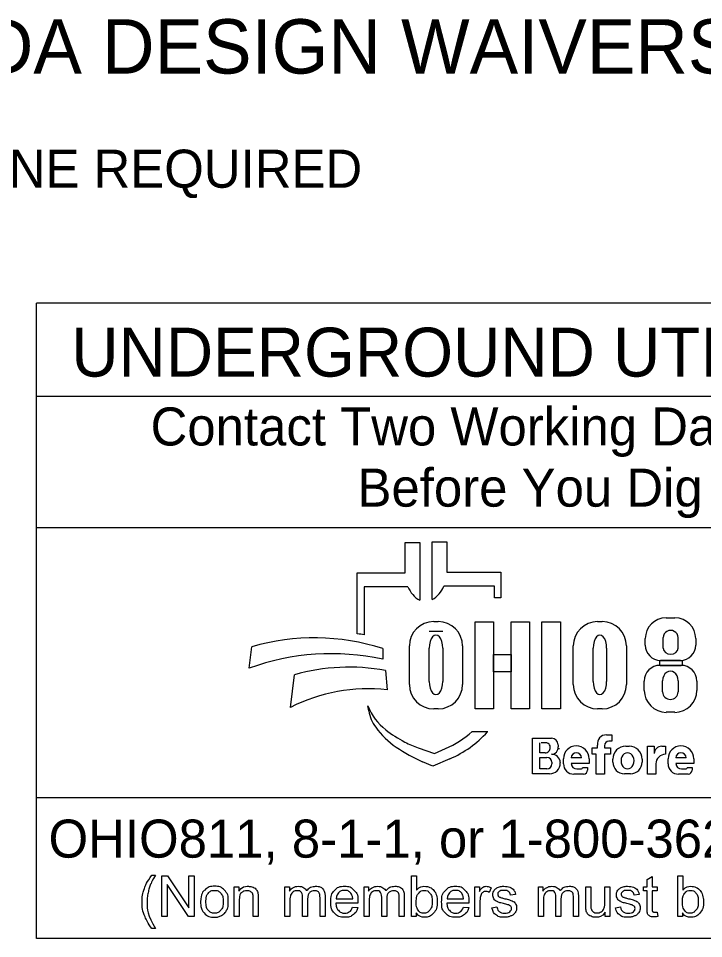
# Model space of a CAD drawing. Extents: x -2.1 to 31.9, y 6.3 to 28.3.
# Drawn here: x 0.246 to 2.766, y 8.487 to 11.873 of the extents above; entities that cross this region are included whole.
import ezdxf

# ---------------------------------------------------------------- set-up
doc = ezdxf.new("R2010")
doc.units = 0
doc.layers.add('SH_Data', color=7, linetype='Continuous')
doc.layers.add('SH_Text', color=7, linetype='Continuous')

msp = doc.modelspace()

# ---------------------------------------------------------------- linework, layer by layer
at = {"layer": 'SH_Data'}
for p, q in [((0.312, 8.4868), (0.312, 10.8243)), ((4.562, 10.8243), (0.312, 10.8243)), ((0.312, 10.4827), (4.562, 10.4827)), ((0.312, 9.9993), (4.562, 9.9993)), ((4.562, 9.0046), (0.312, 9.0046)), ((4.562, 8.4868), (0.312, 8.4868))]:
    msp.add_line(p, q, dxfattribs=at)
at = {"layer": 'SH_Text'}
for p, q in [((1.668, 9.8323), (1.668, 9.9438)), ((1.668, 9.9438), (1.7216, 9.9438)), ((1.7216, 9.9438), (1.7216, 9.7317)), ((1.7673, 9.734), (1.7673, 9.9461)), ((1.7673, 9.9461), (1.8209, 9.9461)), ((1.8209, 9.9461), (1.8209, 9.8346)), ((1.492, 9.6084), (1.492, 9.8323)), ((1.492, 9.8323), (1.668, 9.8323)), ((1.8209, 9.8346), (2.0202, 9.8346)), ((2.0202, 9.8346), (2.0202, 9.7408)), ((1.5173, 9.7808), (1.5173, 9.604)), ((1.6784, 9.7808), (1.5173, 9.7808)), ((1.9969, 9.7831), (1.8105, 9.7831)), ((1.9969, 9.7408), (1.9969, 9.7831)), ((2.0202, 9.7408), (1.9969, 9.7408)), ((1.773, 9.6531), (1.7895, 9.6531)), ((2.376, 9.6531), (2.3926, 9.6531)), ((2.6275, 9.6671), (2.6603, 9.6671)), ((1.8062, 9.6161), (1.7564, 9.6161)), ((2.5512, 9.5665), (2.5512, 9.5908)), ((2.6174, 9.5551), (2.6174, 9.5944)), ((2.6715, 9.5944), (2.6715, 9.5551)), ((2.7366, 9.5908), (2.7366, 9.5665)), ((1.0947, 9.4821), (1.104, 9.5602)), ((1.5853, 9.5537), (1.5853, 9.5149)), ((1.6835, 9.4216), (1.6835, 9.5636)), ((1.7564, 9.433), (1.7564, 9.5553)), ((1.8062, 9.5553), (1.8062, 9.433)), ((1.879, 9.5636), (1.879, 9.4216)), ((2.2865, 9.4216), (2.2865, 9.5636)), ((2.3595, 9.433), (2.3595, 9.5553)), ((2.4092, 9.5553), (2.4092, 9.433)), ((2.482, 9.5636), (2.482, 9.4216)), ((2.6054, 9.4922), (2.6828, 9.4922)), ((2.6806, 9.5105), (2.6072, 9.5105)), ((1.2465, 9.3375), (1.2612, 9.4577)), ((1.5953, 9.4731), (1.6015, 9.4021)), ((2.5475, 9.4002), (2.5475, 9.4343)), ((2.615, 9.3943), (2.615, 9.4352)), ((2.6719, 9.4352), (2.6719, 9.3943)), ((2.7406, 9.4343), (2.7406, 9.4002)), ((1.5342, 9.3246), (1.5311, 9.3426)), ((1.7895, 9.3321), (1.773, 9.3321)), ((2.3926, 9.3321), (2.376, 9.3321)), ((2.6597, 9.3193), (2.6285, 9.3193)), ((1.9145, 9.2488), (1.9719, 9.2488)), ((2.1358, 9.093), (2.1358, 9.2237)), ((2.1358, 9.2237), (2.2069, 9.2237)), ((2.4083, 9.2365), (2.4278, 9.2365)), ((2.4278, 9.2131), (2.4177, 9.2131)), ((2.4278, 9.2365), (2.4278, 9.2135)), ((1.716, 9.1884), (1.7755, 9.1679)), ((1.7755, 9.1679), (1.8165, 9.1857)), ((2.1637, 9.1703), (2.1637, 9.2072)), ((2.1889, 9.2072), (2.1677, 9.2072)), ((2.2307, 9.2), (2.2307, 9.1921)), ((2.3557, 9.1652), (2.3557, 9.1881)), ((2.3557, 9.1881), (2.3751, 9.1881)), ((2.3751, 9.1881), (2.3751, 9.1986)), ((2.4012, 9.1966), (2.4012, 9.1881)), ((2.4012, 9.1881), (2.4227, 9.1881)), ((2.4227, 9.1881), (2.4227, 9.1652)), ((2.4796, 9.1947), (2.4917, 9.1947)), ((2.5598, 9.0918), (2.5598, 9.1945)), ((2.5598, 9.1945), (2.5844, 9.1945)), ((2.5844, 9.1945), (2.5844, 9.1676)), ((2.6116, 9.1945), (2.6255, 9.1945)), ((2.6255, 9.1945), (2.6255, 9.1648)), ((1.8327, 9.1483), (1.7694, 9.1209)), ((2.1831, 9.1703), (2.1637, 9.1703)), ((2.1637, 9.1108), (2.1637, 9.1537)), ((2.1637, 9.1537), (2.1893, 9.1537)), ((2.2503, 9.1298), (2.2503, 9.1482)), ((2.3169, 9.1522), (2.2784, 9.1522)), ((2.3448, 9.1482), (2.3448, 9.1305)), ((2.3707, 9.1652), (2.3557, 9.1652)), ((2.3707, 9.0918), (2.3707, 9.1652)), ((2.4227, 9.1652), (2.4012, 9.1652)), ((2.4012, 9.1652), (2.4012, 9.0918)), ((2.4317, 9.1361), (2.4317, 9.1469)), ((2.5395, 9.1469), (2.5395, 9.1361)), ((2.6352, 9.1298), (2.6352, 9.1482)), ((2.7018, 9.1522), (2.6633, 9.1522)), ((2.7298, 9.1482), (2.7298, 9.1305)), ((1.7694, 9.1209), (1.7321, 9.1373)), ((2.189, 9.1108), (2.1637, 9.1108)), ((2.2074, 9.1356), (2.2074, 9.1292)), ((2.2388, 9.1327), (2.2388, 9.1323)), ((2.3448, 9.1305), (2.2784, 9.1305)), ((2.2993, 9.1113), (2.3135, 9.1113)), ((2.322, 9.1169), (2.3389, 9.1169)), ((2.3389, 9.1169), (2.3389, 9.107)), ((2.5903, 9.1299), (2.5903, 9.0918)), ((2.7298, 9.1305), (2.6633, 9.1305)), ((2.6843, 9.1113), (2.6984, 9.1113)), ((2.707, 9.1169), (2.7238, 9.1169)), ((2.7238, 9.1169), (2.7238, 9.107)), ((2.1994, 9.093), (2.1358, 9.093)), ((2.3237, 9.0918), (2.2883, 9.0918)), ((2.4012, 9.0918), (2.3707, 9.0918)), ((2.4967, 9.0933), (2.4745, 9.0933)), ((2.5903, 9.0918), (2.5598, 9.0918)), ((2.7086, 9.0918), (2.6732, 9.0918))]:
    msp.add_line(p, q, dxfattribs=at)
for points in [[(1.9254, 9.652), (1.9934, 9.652), (1.9934, 9.3321), (1.9254, 9.3321)], [(2.0576, 9.652), (2.1255, 9.652), (2.1255, 9.3321), (2.0576, 9.3321)], [(2.1709, 9.652), (2.2396, 9.652), (2.2396, 9.3321), (2.1709, 9.3321)], [(1.9934, 9.5321), (2.0576, 9.5321), (2.0576, 9.4681), (1.9934, 9.4681)], [(2.6051, 9.5105), (2.6868, 9.5105), (2.6868, 9.492), (2.6051, 9.492)]]:
    msp.add_lwpolyline(points, close=True, dxfattribs=at)
for points in [[(0.7366, 8.7206), (0.7497, 8.7206)], [(0.7733, 8.5679), (0.7733, 8.718), (0.7936, 8.718), (0.8726, 8.6001), (0.8726, 8.718), (0.8916, 8.718), (0.8916, 8.5679), (0.8713, 8.5679), (0.7923, 8.6858), (0.7923, 8.5679), (0.7733, 8.5679)], [(1.7088, 8.5679), (1.6917, 8.5679), (1.6917, 8.718), (1.7101, 8.718), (1.7101, 8.6645)], [(2.5577, 8.5997), (2.5577, 8.6624), (2.5441, 8.6624), (2.5441, 8.6767), (2.5577, 8.6767), (2.5577, 8.7037), (2.5761, 8.7147), (2.5761, 8.6767), (2.5946, 8.6767), (2.5946, 8.6624), (2.5761, 8.6624), (2.5761, 8.5987)], [(2.6878, 8.5679), (2.6708, 8.5679), (2.6708, 8.718), (2.6892, 8.718), (2.6892, 8.6645)], [(1.0393, 8.5679), (1.0393, 8.6767), (1.0559, 8.6767), (1.0559, 8.6613)], [(1.2257, 8.5679), (1.2257, 8.6767), (1.2422, 8.6767), (1.2422, 8.6614)], [(1.5171, 8.5679), (1.5171, 8.6767), (1.5335, 8.6767), (1.5335, 8.6614)], [(1.9248, 8.5679), (1.9248, 8.6767), (1.9414, 8.6767), (1.9414, 8.6602)], [(1.9839, 8.6732), (1.9774, 8.6562)], [(2.1581, 8.5679), (2.1581, 8.6767), (2.1745, 8.6767), (2.1745, 8.6614)], [(2.3324, 8.6093), (2.3324, 8.6767), (2.3508, 8.6767), (2.3508, 8.6164)], [(2.4021, 8.6185), (2.4021, 8.6767), (2.4205, 8.6767), (2.4205, 8.5679), (2.404, 8.5679)], [(1.1276, 8.6348), (1.1276, 8.5679), (1.1092, 8.5679), (1.1092, 8.634)], [(1.3088, 8.6311), (1.3088, 8.5679), (1.2903, 8.5679), (1.2903, 8.6385)], [(1.3732, 8.6426), (1.3732, 8.5679), (1.3548, 8.5679), (1.3548, 8.6364)], [(1.6001, 8.6311), (1.6001, 8.5679), (1.5817, 8.5679), (1.5817, 8.6385)], [(1.6646, 8.6426), (1.6646, 8.5679), (1.6462, 8.5679), (1.6462, 8.6364)], [(2.0738, 8.6486), (2.0558, 8.6462)], [(2.2411, 8.6311), (2.2411, 8.5679), (2.2227, 8.5679), (2.2227, 8.6385)], [(2.3056, 8.6426), (2.3056, 8.5679), (2.2871, 8.5679), (2.2871, 8.6364)], [(2.5284, 8.6486), (2.5103, 8.6462)], [(1.0577, 8.6273), (1.0577, 8.5679), (1.0393, 8.5679)], [(1.2441, 8.6243), (1.2441, 8.5679), (1.2257, 8.5679)], [(1.4944, 8.6176), (1.4133, 8.6176)], [(1.4143, 8.6327), (1.4751, 8.6327)], [(1.4749, 8.603), (1.4939, 8.6006)], [(1.5355, 8.6243), (1.5355, 8.5679), (1.5171, 8.5679)], [(1.9024, 8.6176), (1.8213, 8.6176)], [(1.8223, 8.6327), (1.8831, 8.6327)], [(1.8829, 8.603), (1.9019, 8.6006)], [(1.9433, 8.6249), (1.9433, 8.5679), (1.9248, 8.5679)], [(1.9874, 8.6004), (2.0056, 8.6032)], [(2.1765, 8.6243), (2.1765, 8.5679), (2.1581, 8.5679)], [(2.442, 8.6004), (2.4602, 8.6032)], [(1.7088, 8.5815), (1.7088, 8.5679)], [(2.404, 8.5679), (2.404, 8.584)], [(2.5946, 8.5843), (2.5972, 8.568)], [(2.6878, 8.5815), (2.6878, 8.5679)], [(0.7497, 8.5237), (0.7366, 8.5237)]]:
    msp.add_lwpolyline(points, dxfattribs=at)
for centre, radius, start, end in [((1.7697, 9.8176), 0.0985, 201.9296, 240.7469), ((1.7192, 9.8199), 0.0985, 299.2531, 338.0704), ((1.773, 9.5636), 0.0895, 90, 180), ((1.7895, 9.5636), 0.0895, 0, 90), ((2.376, 9.5636), 0.0895, 90, 180), ((2.3926, 9.5636), 0.0895, 0, 90), ((2.6275, 9.5908), 0.0763, 90, 180), ((2.6603, 9.5908), 0.0763, 0, 90), ((1.3341, 8.7741), 0.8191, 72.1402, 106.3144), ((1.3639, 8.7994), 0.8191, 79.2074, 81.0007), ((2.6072, 9.5665), 0.056, 180, 270), ((2.6806, 9.5665), 0.056, 270, 0), ((1.3972, 8.643), 0.8919, 77.8238, 109.8274), ((1.4611, 8.7533), 0.7322, 79.44, 105.8467), ((2.6054, 9.4343), 0.0579, 90, 180), ((2.6828, 9.4343), 0.0579, 0, 90), ((1.773, 9.4216), 0.0895, 180, 270), ((1.7895, 9.4216), 0.0895, 270, 0), ((2.376, 9.4216), 0.0895, 180, 270), ((2.3926, 9.4216), 0.0895, 270, 0), ((1.5331, 8.7701), 0.6357, 83.8248, 116.8021), ((2.6285, 9.4002), 0.081, 180, 270), ((2.6597, 9.4002), 0.081, 270, 0), ((1.7185, 9.4147), 0.2008, 201.0457, 232.5314), ((1.6755, 9.3487), 0.1433, 189.6817, 216.0884), ((1.8091, 9.4462), 0.3088, 216.0884, 235.7167), ((1.9111, 9.6659), 0.5173, 232.5314, 241.794), ((1.6731, 9.5162), 0.3602, 293.4582, 312.0712), ((1.6731, 9.5162), 0.401, 293.4582, 317.8286), ((1.8259, 9.5071), 0.3371, 241.794, 250.9821), ((2.2069, 9.2), 0.0238, 0, 90), ((2.4083, 9.203), 0.0335, 90, 187.5187), ((2.4177, 9.1966), 0.0165, 90, 180), ((1.9757, 9.6904), 0.6044, 235.7167, 246.2325), ((2.1831, 9.189), 0.0187, 270, 2.0582), ((2.185, 9.1903), 0.0169, 357.8325, 90), ((2.2065, 9.1893), 0.0243, 270, 6.6529), ((2.2171, 9.1878), 0.0175, 347.4023, 0), ((2.2976, 9.1482), 0.0473, 0, 180), ((2.4796, 9.1469), 0.0478, 90, 180), ((2.4917, 9.1469), 0.0478, 0, 90), ((2.6112, 9.1676), 0.0269, 89.2449, 180), ((2.6825, 9.1482), 0.0473, 0, 180), ((2.1893, 9.1356), 0.0181, 0, 90), ((2.2067, 9.1329), 0.0321, 4.0748, 90), ((2.2976, 9.1512), 0.0193, 2.9632, 177.0368), ((2.6252, 9.1299), 0.0349, 89.6033, 180), ((2.6825, 9.1512), 0.0193, 2.9632, 177.0368), ((2.189, 9.1292), 0.0184, 270, 0), ((2.1994, 9.1323), 0.0393, 270, 0), ((2.2058, 9.1327), 0.033, 0, 11.7502), ((2.2883, 9.1298), 0.038, 180, 270), ((2.2993, 9.1323), 0.021, 184.827, 270), ((2.3135, 9.1207), 0.00938, 270, 335.9979), ((2.4745, 9.1361), 0.0428, 180, 270), ((2.4967, 9.1361), 0.0428, 270, 0), ((2.6732, 9.1298), 0.038, 180, 270), ((2.6843, 9.1323), 0.021, 184.827, 270), ((2.6984, 9.1207), 0.00938, 270, 335.9979), ((2.3237, 9.107), 0.0152, 270, 0), ((2.7086, 9.107), 0.0152, 270, 0)]:
    msp.add_arc(centre, radius, start, end, dxfattribs=at)
for centre, major_axis, ratio, start_param, end_param in [((2.6445, 9.5944), (0.0271, 0), 0.969373, 0, 3.141593), ((1.7813, 9.5553), (0, 0.0484), 0.514403, 4.712389, 7.853982), ((2.3843, 9.5553), (0, 0.0484), 0.514403, 4.712389, 7.853982), ((2.6445, 9.5551), (0.0271, 0), 0.818453, 3.141593, 6.283185), ((2.6435, 9.4352), (0, 0.0358), 0.794529, 4.712389, 7.853982), ((1.7813, 9.433), (0, 0.0484), 0.514403, 1.570796, 4.712389), ((2.3843, 9.433), (0, 0.0484), 0.514403, 1.570796, 4.712389), ((2.6435, 9.3943), (0.0284, 0), 0.959837, 3.141593, 6.283185), ((2.4861, 9.1415), (0, 0.029), 0.832186, 4.712389, 7.853982), ((2.4861, 9.1415), (0, 0.0302), 0.797287, 1.570796, 4.712389)]:
    msp.add_ellipse(centre, major_axis=major_axis, ratio=ratio, start_param=start_param, end_param=end_param, dxfattribs=at)
for points in [[(0.7366, 8.5237), (0.7213, 8.543), (0.7107, 8.5688), (0.7002, 8.5946), (0.7002, 8.6222), (0.7002, 8.6466), (0.7081, 8.6689), (0.7173, 8.6948), (0.7366, 8.7206)], [(0.7497, 8.7206), (0.7374, 8.6993), (0.7334, 8.6901), (0.7271, 8.676), (0.7236, 8.6606), (0.7192, 8.6415), (0.7192, 8.6221), (0.7192, 8.5729), (0.7497, 8.5237)], [(0.9158, 8.6223), (0.9158, 8.6525), (0.9326, 8.667), (0.9466, 8.6791), (0.9668, 8.6791), (0.9892, 8.6791), (1.0034, 8.6644), (1.0176, 8.6497), (1.0176, 8.6238), (1.0176, 8.6029), (1.0114, 8.5908), (1.0051, 8.5788), (0.993, 8.5721), (0.981, 8.5655), (0.9668, 8.5655), (0.9439, 8.5655), (0.9299, 8.5801), (0.9158, 8.5948), (0.9158, 8.6223)], [(1.0559, 8.6613), (1.0678, 8.6791), (1.0905, 8.6791), (1.1003, 8.6791), (1.1085, 8.6756), (1.1168, 8.6721), (1.1209, 8.6663), (1.125, 8.6606), (1.1266, 8.6527), (1.1276, 8.6476), (1.1276, 8.6348)], [(1.2422, 8.6614), (1.2473, 8.6694), (1.2558, 8.6742), (1.2643, 8.6791), (1.2752, 8.6791), (1.2873, 8.6791), (1.295, 8.6741), (1.3027, 8.6691), (1.3059, 8.66), (1.3188, 8.6791), (1.3396, 8.6791), (1.3558, 8.6791), (1.3645, 8.6702), (1.3732, 8.6612), (1.3732, 8.6426)], [(1.4939, 8.6006), (1.4894, 8.5839), (1.4772, 8.5747), (1.465, 8.5655), (1.4461, 8.5655), (1.4222, 8.5655), (1.4083, 8.5802), (1.3943, 8.5949), (1.3943, 8.6214), (1.3943, 8.6488), (1.4084, 8.664), (1.4225, 8.6791), (1.4451, 8.6791), (1.4669, 8.6791), (1.4807, 8.6643), (1.4945, 8.6494), (1.4945, 8.6225), (1.4945, 8.6208), (1.4944, 8.6176)], [(1.5335, 8.6614), (1.5387, 8.6694), (1.5472, 8.6742), (1.5557, 8.6791), (1.5665, 8.6791), (1.5786, 8.6791), (1.5864, 8.6741), (1.5941, 8.6691), (1.5973, 8.66), (1.6102, 8.6791), (1.6309, 8.6791), (1.6471, 8.6791), (1.6559, 8.6702), (1.6646, 8.6612), (1.6646, 8.6426)], [(1.7101, 8.6645), (1.7218, 8.6791), (1.7399, 8.6791), (1.75, 8.6791), (1.7589, 8.6751), (1.7679, 8.671), (1.7737, 8.6637), (1.7795, 8.6564), (1.7827, 8.6461), (1.786, 8.6357), (1.786, 8.6239), (1.786, 8.596), (1.7722, 8.5807), (1.7584, 8.5655), (1.739, 8.5655), (1.7197, 8.5655), (1.7088, 8.5815)], [(1.9019, 8.6006), (1.8974, 8.5839), (1.8852, 8.5747), (1.873, 8.5655), (1.8541, 8.5655), (1.8302, 8.5655), (1.8163, 8.5802), (1.8023, 8.5949), (1.8023, 8.6214), (1.8023, 8.6488), (1.8164, 8.664), (1.8305, 8.6791), (1.8531, 8.6791), (1.8749, 8.6791), (1.8887, 8.6643), (1.9025, 8.6494), (1.9025, 8.6225), (1.9025, 8.6208), (1.9024, 8.6176)], [(1.9414, 8.6602), (1.9478, 8.6718), (1.9531, 8.6754), (1.9585, 8.6791), (1.965, 8.6791), (1.9743, 8.6791), (1.9839, 8.6732)], [(2.0056, 8.6032), (2.0072, 8.5923), (2.0142, 8.5864), (2.0213, 8.5806), (2.0339, 8.5806), (2.0466, 8.5806), (2.0528, 8.5858), (2.059, 8.5909), (2.059, 8.5979), (2.059, 8.6042), (2.0535, 8.6078), (2.0497, 8.6102), (2.0346, 8.614), (2.0143, 8.6192), (2.0065, 8.6229), (1.9986, 8.6266), (1.9946, 8.6332), (1.9905, 8.6398), (1.9905, 8.6478), (1.9905, 8.6551), (1.9939, 8.6613), (1.9972, 8.6675), (2.0029, 8.6716), (2.0073, 8.6747), (2.0147, 8.6769), (2.0221, 8.6791), (2.0306, 8.6791), (2.0435, 8.6791), (2.0532, 8.6754), (2.0629, 8.6717), (2.0675, 8.6654), (2.0721, 8.6591), (2.0738, 8.6486)], [(2.1745, 8.6614), (2.1797, 8.6694), (2.1882, 8.6742), (2.1967, 8.6791), (2.2075, 8.6791), (2.2196, 8.6791), (2.2274, 8.6741), (2.2351, 8.6691), (2.2383, 8.66), (2.2512, 8.6791), (2.2719, 8.6791), (2.2881, 8.6791), (2.2969, 8.6702), (2.3056, 8.6612), (2.3056, 8.6426)], [(2.4602, 8.6032), (2.4617, 8.5923), (2.4688, 8.5864), (2.4758, 8.5806), (2.4885, 8.5806), (2.5012, 8.5806), (2.5074, 8.5858), (2.5135, 8.5909), (2.5135, 8.5979), (2.5135, 8.6042), (2.5081, 8.6078), (2.5043, 8.6102), (2.4892, 8.614), (2.4689, 8.6192), (2.4611, 8.6229), (2.4532, 8.6266), (2.4492, 8.6332), (2.4451, 8.6398), (2.4451, 8.6478), (2.4451, 8.6551), (2.4484, 8.6613), (2.4518, 8.6675), (2.4575, 8.6716), (2.4618, 8.6747), (2.4693, 8.6769), (2.4767, 8.6791), (2.4852, 8.6791), (2.498, 8.6791), (2.5077, 8.6754), (2.5174, 8.6717), (2.5221, 8.6654), (2.5267, 8.6591), (2.5284, 8.6486)], [(2.6892, 8.6645), (2.7009, 8.6791), (2.719, 8.6791), (2.729, 8.6791), (2.738, 8.6751), (2.747, 8.671), (2.7527, 8.6637), (2.7585, 8.6564), (2.7618, 8.6461), (2.7651, 8.6357), (2.7651, 8.6239), (2.7651, 8.596), (2.7513, 8.5807), (2.7374, 8.5655), (2.7181, 8.5655), (2.6988, 8.5655), (2.6878, 8.5815)], [(0.9348, 8.6223), (0.9348, 8.6014), (0.9439, 8.591), (0.953, 8.5806), (0.9668, 8.5806), (0.9805, 8.5806), (0.9896, 8.591), (0.9986, 8.6015), (0.9986, 8.6229), (0.9986, 8.6431), (0.9895, 8.6535), (0.9804, 8.6639), (0.9668, 8.6639), (0.953, 8.6639), (0.9439, 8.6536), (0.9348, 8.6432), (0.9348, 8.6223)], [(1.1092, 8.634), (1.1092, 8.6453), (1.1071, 8.6509), (1.1049, 8.6564), (1.0994, 8.6598), (1.0939, 8.6631), (1.0866, 8.6631), (1.0748, 8.6631), (1.0663, 8.6556), (1.0577, 8.6482), (1.0577, 8.6273)], [(1.2903, 8.6385), (1.2903, 8.6508), (1.2858, 8.657), (1.2813, 8.6631), (1.2711, 8.6631), (1.2633, 8.6631), (1.2567, 8.659), (1.2501, 8.6549), (1.2471, 8.647), (1.2441, 8.6391), (1.2441, 8.6243)], [(1.3548, 8.6364), (1.3548, 8.6474), (1.353, 8.6523), (1.3512, 8.6572), (1.3465, 8.6601), (1.3418, 8.6631), (1.3354, 8.6631), (1.3239, 8.6631), (1.3164, 8.6555), (1.3088, 8.6478), (1.3088, 8.6311)], [(1.4751, 8.6327), (1.4738, 8.6464), (1.4681, 8.6533), (1.4593, 8.664), (1.4453, 8.664), (1.4325, 8.664), (1.4239, 8.6555), (1.4152, 8.647), (1.4143, 8.6327)], [(1.5817, 8.6385), (1.5817, 8.6508), (1.5772, 8.657), (1.5727, 8.6631), (1.5624, 8.6631), (1.5547, 8.6631), (1.548, 8.659), (1.5414, 8.6549), (1.5385, 8.647), (1.5355, 8.6391), (1.5355, 8.6243)], [(1.6462, 8.6364), (1.6462, 8.6474), (1.6444, 8.6523), (1.6426, 8.6572), (1.6379, 8.6601), (1.6331, 8.6631), (1.6268, 8.6631), (1.6153, 8.6631), (1.6077, 8.6555), (1.6001, 8.6478), (1.6001, 8.6311)], [(1.7085, 8.6231), (1.7085, 8.6035), (1.7139, 8.5948), (1.7225, 8.5806), (1.7374, 8.5806), (1.7494, 8.5806), (1.7582, 8.5911), (1.767, 8.6016), (1.767, 8.6224), (1.767, 8.6437), (1.7586, 8.6539), (1.7502, 8.664), (1.7382, 8.664), (1.7261, 8.664), (1.7173, 8.6535), (1.7085, 8.643), (1.7085, 8.6231)], [(1.8831, 8.6327), (1.8818, 8.6464), (1.8761, 8.6533), (1.8673, 8.664), (1.8532, 8.664), (1.8405, 8.664), (1.8319, 8.6555), (1.8232, 8.647), (1.8223, 8.6327)], [(1.9774, 8.6562), (1.9707, 8.6601), (1.964, 8.6601), (1.958, 8.6601), (1.9532, 8.6565), (1.9484, 8.6529), (1.9463, 8.6464), (1.9433, 8.6366), (1.9433, 8.6249)], [(2.0558, 8.6462), (2.0545, 8.6546), (2.0486, 8.6593), (2.0427, 8.664), (2.032, 8.664), (2.0193, 8.664), (2.0138, 8.6598), (2.0084, 8.6556), (2.0084, 8.65), (2.0084, 8.6464), (2.0106, 8.6435), (2.0129, 8.6405), (2.0177, 8.6386), (2.0205, 8.6375), (2.034, 8.6339), (2.0536, 8.6286), (2.0614, 8.6253), (2.0691, 8.622), (2.0735, 8.6156), (2.078, 8.6093), (2.078, 8.5999), (2.078, 8.5907), (2.0726, 8.5825), (2.0672, 8.5744), (2.057, 8.5699), (2.0469, 8.5655), (2.034, 8.5655), (2.0128, 8.5655), (2.0017, 8.5743), (1.9905, 8.5831), (1.9874, 8.6004)], [(2.2227, 8.6385), (2.2227, 8.6508), (2.2182, 8.657), (2.2137, 8.6631), (2.2034, 8.6631), (2.1957, 8.6631), (2.189, 8.659), (2.1824, 8.6549), (2.1795, 8.647), (2.1765, 8.6391), (2.1765, 8.6243)], [(2.2871, 8.6364), (2.2871, 8.6474), (2.2854, 8.6523), (2.2836, 8.6572), (2.2789, 8.6601), (2.2741, 8.6631), (2.2678, 8.6631), (2.2563, 8.6631), (2.2487, 8.6555), (2.2411, 8.6478), (2.2411, 8.6311)], [(2.5103, 8.6462), (2.5091, 8.6546), (2.5032, 8.6593), (2.4973, 8.664), (2.4865, 8.664), (2.4738, 8.664), (2.4684, 8.6598), (2.463, 8.6556), (2.463, 8.65), (2.463, 8.6464), (2.4652, 8.6435), (2.4675, 8.6405), (2.4723, 8.6386), (2.4751, 8.6375), (2.4886, 8.6339), (2.5082, 8.6286), (2.5159, 8.6253), (2.5237, 8.622), (2.5281, 8.6156), (2.5325, 8.6093), (2.5325, 8.5999), (2.5325, 8.5907), (2.5271, 8.5825), (2.5218, 8.5744), (2.5116, 8.5699), (2.5014, 8.5655), (2.4886, 8.5655), (2.4674, 8.5655), (2.4562, 8.5743), (2.4451, 8.5831), (2.442, 8.6004)], [(2.6876, 8.6231), (2.6876, 8.6035), (2.6929, 8.5948), (2.7016, 8.5806), (2.7164, 8.5806), (2.7285, 8.5806), (2.7373, 8.5911), (2.7461, 8.6016), (2.7461, 8.6224), (2.7461, 8.6437), (2.7377, 8.6539), (2.7292, 8.664), (2.7173, 8.664), (2.7052, 8.664), (2.6964, 8.6535), (2.6876, 8.643), (2.6876, 8.6231)], [(1.4133, 8.6176), (1.4143, 8.5996), (1.4234, 8.5901), (1.4325, 8.5806), (1.4462, 8.5806), (1.4563, 8.5806), (1.4635, 8.5859), (1.4707, 8.5913), (1.4749, 8.603)], [(1.8213, 8.6176), (1.8223, 8.5996), (1.8314, 8.5901), (1.8405, 8.5806), (1.8542, 8.5806), (1.8643, 8.5806), (1.8715, 8.5859), (1.8787, 8.5913), (1.8829, 8.603)], [(2.404, 8.584), (2.3913, 8.5655), (2.3695, 8.5655), (2.3599, 8.5655), (2.3516, 8.5692), (2.3432, 8.5729), (2.3392, 8.5784), (2.3351, 8.584), (2.3335, 8.5921), (2.3324, 8.5975), (2.3324, 8.6093)], [(2.3508, 8.6164), (2.3508, 8.602), (2.3519, 8.597), (2.3537, 8.5897), (2.3593, 8.5855), (2.3649, 8.5814), (2.3732, 8.5814), (2.3815, 8.5814), (2.3888, 8.5856), (2.396, 8.5899), (2.3991, 8.5972), (2.4021, 8.6045), (2.4021, 8.6185)], [(2.5972, 8.568), (2.5894, 8.5664), (2.5833, 8.5664), (2.5733, 8.5664), (2.5677, 8.5696), (2.5622, 8.5728), (2.56, 8.5779), (2.5577, 8.5831), (2.5577, 8.5997)], [(2.5761, 8.5987), (2.5761, 8.5908), (2.5771, 8.5885), (2.5781, 8.5862), (2.5803, 8.5849), (2.5825, 8.5836), (2.5865, 8.5836), (2.5896, 8.5836), (2.5946, 8.5843)]]:
    msp.add_open_spline(points, degree=3, dxfattribs=at)

# ---------------------------------------------------------------- texts
for s, height, p in [('ADA DESIGN WAIVERS', 0.2, (-0.0711, 11.6696)), ('NONE REQUIRED', 0.14, (-0.0711, 11.2496)), ('UNDERGROUND UTILITIES', 0.18, (0.4401, 10.5546)), ('Contact Two Working Days', 0.14, (0.7316, 10.3011)), ('Before You Dig', 0.14, (1.4928, 10.0761)), ('OHIO811, 8-1-1, or 1-800-362-2764', 0.14, (0.3564, 8.7846))]:
    msp.add_text(s, height=height, dxfattribs=at).set_placement(p)

doc.saveas('drawing.dxf')
